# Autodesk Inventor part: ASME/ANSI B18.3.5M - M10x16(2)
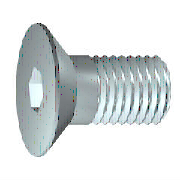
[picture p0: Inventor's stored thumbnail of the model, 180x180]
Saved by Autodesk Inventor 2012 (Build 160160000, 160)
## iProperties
Created: 2011-02
Part Number: ASME/ANSI B18.3.5M - M10x16(2)
Material: Steel, Mild
Description: Broached Hexagon Socket Flat Countersunk Head Cap Screws - Metric
Document SubType Name: Modeling
Standard: ASME/ANSI B18.3.5M
Designer: jrr70267
Standard Revision: 1986
Standards Organization: ANSI
Language: en-US
Size Designation: M10x16
Categories: <MemberInstance><Categories><Category DisplayName="Fasteners" InternalName="e4da775c-781d-43d5-af7c-5136215cf5a6" Mnemonic="FSTN"><Category DisplayName="Bolts"
Density: 7.86 g/cm^3
IsCustomPart: 0
Author: jrr70267
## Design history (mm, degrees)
sketch "Sketch2"
  geometry: L1 (0, -16)-(-5, -16); L2 (0, 0)-(0, -16); L3 (-9.75, 0)-(0, 0); L4 (-9.75, -1.45)-(-9.75, 0); L5 (-5, -6.2)-(-9.75, -1.45); L6 (-5, -16)-(-5, -6.2); L7 (0, 0)-(0, -16); 1 further point
  constraints: 14 end point, 3 vertical, 2 horizontal, 1 coincident
  dimensions: "d2" = 45 deg angle of L5 L2; "d4" = 5 distance of L1.start L1.end (= 0.5 x NND); "d6" = 9.75 distance of L3.start L2.start (= 0.5 x ParA); "d8" = 6.2 vertical distance of L2.start L5.start (= ParH); "d10" = 16 distance of L2.start L1.start (= NLG)
fillet "Fillet1" dims "d24" = 0.8 (= Rr)
chamfer "Chamfer1" distance "d25" = 0.75 (= 0.5 x PTC); stored, may be unused: second distance "d26" = 0.75 (= 0.5 x PTC), angle "d41" = 45 deg
sketch "Sketch4"
  geometry: L1 (-3, -1.732)-(-3, 1.732); L2 (-3, 1.732)-(0, 3.464); L3 (0, 3.464)-(3, 1.732); L4 (3, 1.732)-(3, -1.732); L5 (3, -1.732)-(0, -3.464); L6 (0, -3.464)-(-3, -1.732); C1 r 9.75 at (0, 0) reference; C2 r 3 at (0, 0)
  constraints: 12 end point, 6 tangent, 4 equal length, 1 centre point, 1 coincident, 1 parallel, 1 vertical
  dimensions: "d27" = 6 diameter of C2 (= ParJ)
extrude "Extrusion2" cut sketch "Sketch4" distance "d39" = 3.6 (= Tt); taper "d40" = 0 deg
node "MSC_A1"
node "MSC_PF1"
node "MSC_PT1"
body "Solid1"
revolve "Revolution1" stored, may be unused: angle "d11" = 360 deg
extrude "Extrusion1" cut sketch "Sketch4" distance "d28" = 3.6 (= Tt); taper "d29" = 0 deg
thread "Thread1" dims "d31" = 6.8 (= Lt), "d32" = 0
sketch "Sketch5"
  geometry: C1 r 9.75 at (0, 0) reference; C2 r 3.03 at (0, 0)
  constraints: 1 centre point, 1 coincident
  dimensions: "d38" = 6.06 diameter of C2 (= 1.01 x ParJ)
other parameters: "NLG" = 16 [user parameter; used in 1 equation term], "PTC" = 1.5 [user parameter; used in 2 equation terms], "ParA" = 19.5 [user parameter; used in 1 equation term], "ParH" = 6.2 [user parameter; used in 1 equation term], "ParJ" = 6 [user parameter; used in 3 equation terms], "Tt" = 3.6 [user parameter; used in 2 equation terms], "Rr" = 0.8 [user parameter; used in 1 equation term], "msp_e" = 1.73205 (= 0.288675 x ParJ) [user parameter], "d1" = 40 deg (derived), "d3" = 9 (derived), "d5" = 14 (derived), "d7" = 8 (derived), "d14" = 0 (derived), "d16" = 120 deg (derived), "d18" = 120 deg (derived), "d19" = 120 deg (derived), "d20" = 5.7735 (derived), "d21" = 14.6647 (derived), "d34" = 0, "d42" = 0, "d43" = 0, "d44" = 0, "Lt" = 6.8 [user parameter; used in 1 equation term]
